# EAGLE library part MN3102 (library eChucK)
MN3102 Clock / Driver
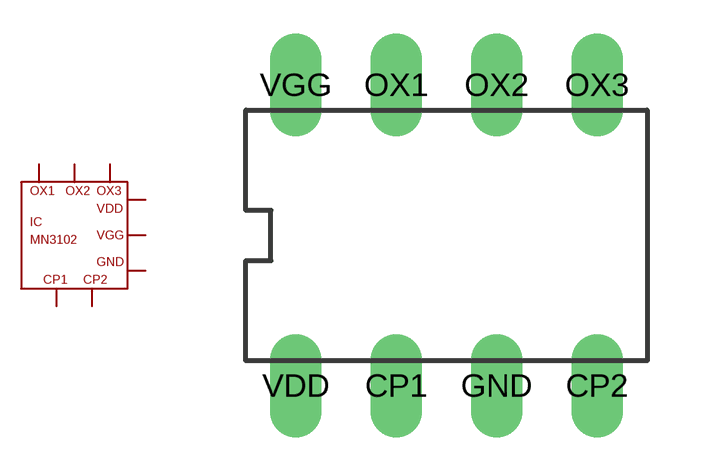
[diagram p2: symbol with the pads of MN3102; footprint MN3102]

Designator prefix IC

## MN3102  [MN3102]
CP1  CP1
CP2  CP2
GND  GND
OX1  OX1
OX2  OX2
OX3  OX3
VDD  VDD
VGG  VGG

## Footprint MN3102 (pad centres in mm)
drill 0.8 long: CP1 -1.27,-3.81; CP2 3.81,-3.81; GND 1.27,-3.81; OX1 -1.27,3.81; OX2 1.27,3.81; OX3 3.81,3.81; VDD -3.81,-3.81; VGG -3.81,3.81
